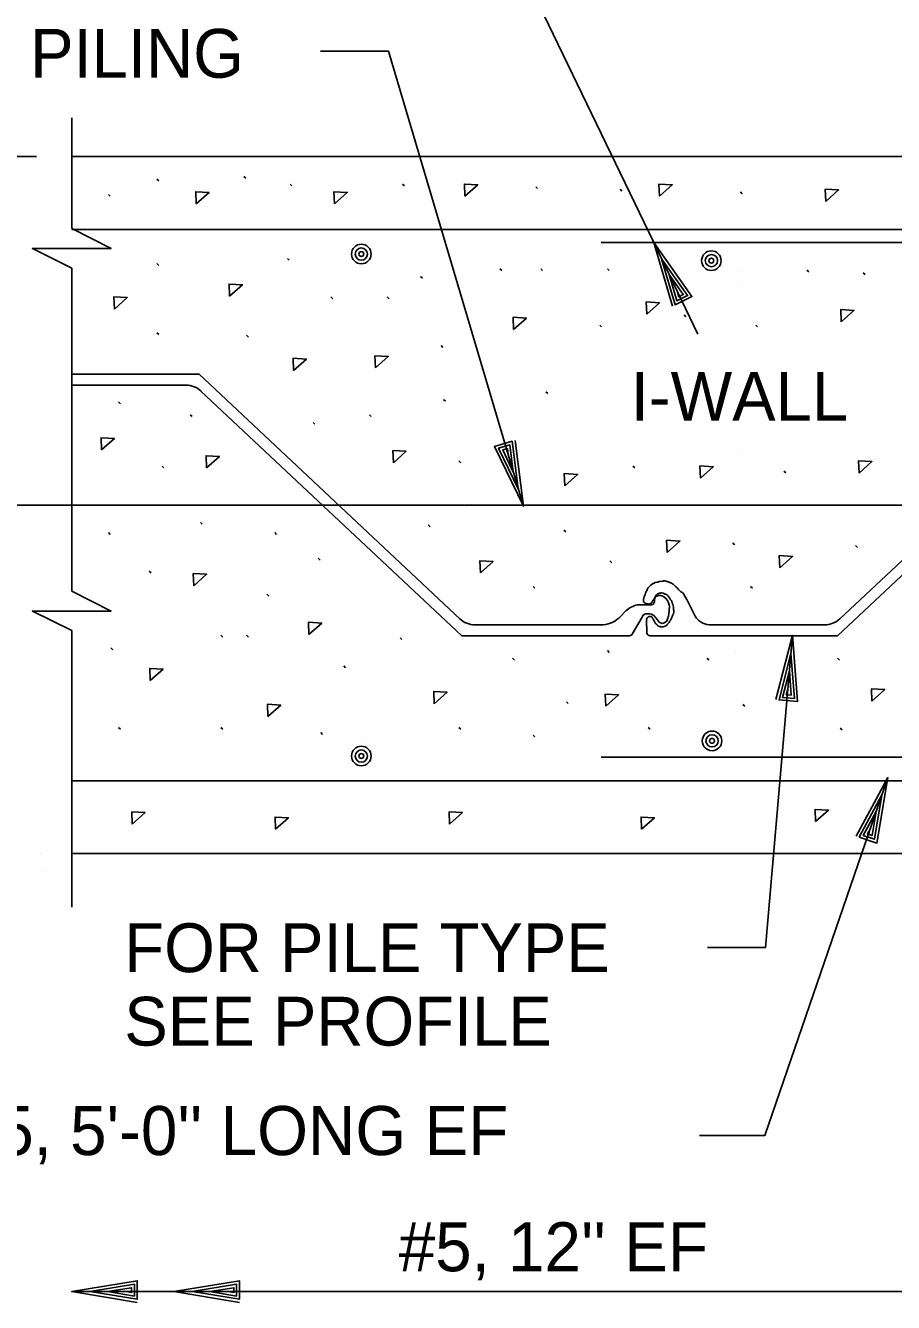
# Model space of a CAD drawing. Extents: x 22369.6 to 22428.3, y 22369.6 to 22415.
# Drawn here: x 22406.186 to 22409.492, y 22375.946 to 22380.805 of the extents above; entities that cross this region are included whole.
import ezdxf

# ---------------------------------------------------------------- set-up
doc = ezdxf.new("R2010")
doc.units = 0
for name, color, linetype in [('Level 1', 7, 'Continuous'), ('Level 10', 7, 'Continuous'), ('Level 2', 7, 'Continuous'), ('Level 4', 7, 'Continuous'), ('Level 8', 7, 'Continuous')]:
    doc.layers.add(name, color=color, linetype=linetype)

msp = doc.modelspace()

# ---------------------------------------------------------------- linework, layer by layer
at = {"layer": 'Level 1'}
for p, q in [((22406.3621, 22380.0321), (22406.3621, 22380.4539)), ((22406.2282, 22380.307), (22404.8457, 22380.307)), ((22408.5786, 22379.9799), (22408.5786, 22379.9799)), ((22408.6087, 22379.9175), (22408.6087, 22379.9175)), ((22406.3621, 22378.6522), (22406.3621, 22379.8821)), ((22408.9125, 22379.8706), (22408.9125, 22379.8706)), ((22408.9125, 22379.8267), (22408.9125, 22379.8267)), ((22408.9125, 22379.1883), (22408.9125, 22379.1883)), ((22408.9125, 22379.1193), (22408.9125, 22379.1193)), ((22407.9229, 22379.0406), (22407.9229, 22379.0406)), ((22408.0626, 22379.0419), (22408.0626, 22379.0419)), ((22405.5525, 22378.9803), (22411.9528, 22378.9803)), ((22407.8835, 22378.9836), (22407.8835, 22378.9836)), ((22408.0823, 22378.9754), (22408.0823, 22378.9754)), ((22406.3621, 22377.4502), (22406.3621, 22378.5022)), ((22408.9256, 22378.4828), (22408.9256, 22378.4828)), ((22409.1068, 22378.4847), (22409.1068, 22378.4847)), ((22408.8902, 22378.4236), (22408.8902, 22378.4236)), ((22409.1009, 22378.4156), (22409.1009, 22378.4156)), ((22408.8067, 22378.1314), (22408.8067, 22378.1314)), ((22407.4709, 22378.0812), (22407.4709, 22378.0812)), ((22408.7609, 22378.0873), (22408.7609, 22378.0873)), ((22407.4251, 22378.0296), (22407.4251, 22378.0296)), ((22409.4706, 22377.943), (22409.4706, 22377.943)), ((22409.448, 22377.8775), (22409.448, 22377.8775)), ((22406.2415, 22377.6528), (22406.2415, 22377.6528)), ((22406.2516, 22377.5845), (22406.2516, 22377.5845)), ((22406.9901, 22376.0149), (22406.9901, 22376.0149)), ((22407.0007, 22376.0283), (22407.0007, 22376.0283)), ((22406.3621, 22375.9869), (22410.1316, 22375.9869)), ((22406.3621, 22375.9869), (22406.3621, 22375.9869)), ((22406.4314, 22375.9869), (22406.4314, 22375.9869)), ((22406.9567, 22375.9869), (22406.9567, 22375.9869)), ((22406.9794, 22376.0016), (22406.9794, 22376.0016)), ((22406.9794, 22375.9829), (22406.9794, 22375.9829)), ((22406.9901, 22375.9696), (22406.9901, 22375.9696)), ((22407.0007, 22375.9576), (22407.0007, 22375.9576)), ((22407.0007, 22375.9456), (22407.0007, 22375.9456))]:
    msp.add_line(p, q, dxfattribs=at)
for points in [[(22407.6267, 22381.4145), (22407.8863, 22381.4145), (22408.5786, 22379.9799)], [(22407.3094, 22380.7069), (22407.5689, 22380.7069), (22408.0823, 22378.9754)], [(22408.5786, 22379.9799), (22408.7473, 22379.6304)], [(22408.6497, 22379.7374), (22408.5786, 22379.9799), (22408.7242, 22379.7734), (22408.6605, 22379.7426), (22408.6087, 22379.9175), (22408.7075, 22379.7772), (22408.6667, 22379.7575), (22408.6377, 22379.8575), (22408.6909, 22379.781), (22408.6741, 22379.7729), (22408.6678, 22379.795)], [(22408.0511, 22379.2262), (22408.0823, 22378.9754), (22407.9718, 22379.2027), (22408.0396, 22379.2228), (22408.0626, 22379.0419), (22407.9876, 22379.1963), (22408.0311, 22379.2091), (22408.0437, 22379.1058), (22408.0034, 22379.1898), (22408.0213, 22379.1951), (22408.024, 22379.1723)], [(22408.7831, 22377.2969), (22409.0046, 22377.2969), (22409.1068, 22378.4847)], [(22409.0443, 22378.2398), (22409.1068, 22378.4847), (22409.1266, 22378.2327), (22409.0562, 22378.2388), (22409.1009, 22378.4156), (22409.1143, 22378.2445), (22409.0691, 22378.2484), (22409.0952, 22378.3492), (22409.1019, 22378.2563), (22409.0833, 22378.2579), (22409.0892, 22378.2801)], [(22408.753, 22376.5806), (22409.0014, 22376.5806), (22409.4706, 22377.943)], [(22409.3503, 22377.7207), (22409.4706, 22377.943), (22409.4285, 22377.6938), (22409.3617, 22377.7168), (22409.448, 22377.8775), (22409.4194, 22377.7082), (22409.3765, 22377.723), (22409.4263, 22377.8144), (22409.4102, 22377.7227), (22409.3926, 22377.7287), (22409.4037, 22377.7489)], [(22406.6114, 22375.9456), (22406.3621, 22375.9869), (22406.6114, 22376.0283), (22406.6114, 22375.9576), (22406.4314, 22375.9869), (22406.6007, 22376.0149), (22406.6007, 22375.9696), (22406.4981, 22375.9869), (22406.5901, 22376.0016), (22406.5901, 22375.9829), (22406.5674, 22375.9869)], [(22407.0007, 22375.9456), (22406.7514, 22375.9869), (22407.0007, 22376.0283), (22407.0007, 22375.9576), (22406.8207, 22375.9869), (22406.9901, 22376.0149), (22406.9901, 22375.9696), (22406.8874, 22375.9869), (22406.9794, 22376.0016), (22406.9794, 22375.9829), (22406.9567, 22375.9869)]]:
    msp.add_lwpolyline(points, dxfattribs=at)
at = {"layer": 'Level 10'}
for p, q in [((22406.3621, 22380.307), (22410.3497, 22380.307)), ((22406.3621, 22380.0292), (22411.6716, 22380.0292)), ((22408.3785, 22379.9799), (22411.6681, 22379.9799)), ((22408.3785, 22378.0214), (22411.15, 22378.0214)), ((22406.3621, 22377.9313), (22411.1526, 22377.9313)), ((22406.3621, 22377.6536), (22411.3171, 22377.6536))]:
    msp.add_line(p, q, dxfattribs=at)
at = {"layer": 'Level 2'}
for p, q in [((22406.3621, 22379.4778), (22406.8468, 22379.4778)), ((22406.8468, 22379.4778), (22407.8413, 22378.5463)), ((22409.2862, 22378.5463), (22410.2807, 22379.4778)), ((22406.7977, 22379.4363), (22406.3621, 22379.4363)), ((22406.854, 22379.4142), (22407.8484, 22378.4828)), ((22409.279, 22378.4828), (22410.2735, 22379.4142)), ((22408.5164, 22378.6009), (22408.563, 22378.6007)), ((22408.7046, 22378.6214), (22408.7359, 22378.5577)), ((22408.452, 22378.5564), (22408.4721, 22378.578)), ((22408.4969, 22378.4887), (22408.5351, 22378.5534)), ((22408.5519, 22378.4964), (22408.5517, 22378.541)), ((22407.8976, 22378.5242), (22408.3876, 22378.5242)), ((22409.2299, 22378.5242), (22408.7896, 22378.5242)), ((22407.8484, 22378.4828), (22408.4867, 22378.4828)), ((22408.5639, 22378.4828), (22409.279, 22378.4828))]:
    msp.add_line(p, q, dxfattribs=at)
for points in [[(22408.5719, 22378.6096), (22408.5708, 22378.6085), (22408.5681, 22378.6068), (22408.5675, 22378.6068), (22408.5653, 22378.6047), (22408.5635, 22378.6042), (22408.563, 22378.6037), (22408.5598, 22378.6035), (22408.5587, 22378.6035), (22408.5572, 22378.6038), (22408.5562, 22378.6038), (22408.5547, 22378.6042), (22408.5537, 22378.604), (22408.5529, 22378.6043), (22408.552, 22378.6045), (22408.5502, 22378.6053), (22408.548, 22378.6058), (22408.5469, 22378.6063), (22408.5462, 22378.6068), (22408.5454, 22378.6076), (22408.5422, 22378.6095), (22408.5411, 22378.61), (22408.5407, 22378.6108), (22408.5397, 22378.6116), (22408.5392, 22378.6129), (22408.5391, 22378.6158), (22408.5394, 22378.6191), (22408.5396, 22378.6222), (22408.5401, 22378.6236), (22408.5404, 22378.6251), (22408.5409, 22378.6265), (22408.5409, 22378.6284), (22408.5437, 22378.6337), (22408.5449, 22378.6367), (22408.5449, 22378.6377), (22408.5454, 22378.6393), (22408.5456, 22378.6403), (22408.5472, 22378.6443), (22408.5482, 22378.6473), (22408.5497, 22378.6512), (22408.5504, 22378.6521), (22408.5519, 22378.6536), (22408.5537, 22378.6572), (22408.5543, 22378.6592), (22408.5555, 22378.6619), (22408.5567, 22378.6639), (22408.557, 22378.6645), (22408.5575, 22378.6657), (22408.5582, 22378.6667), (22408.5597, 22378.668), (22408.5618, 22378.6695), (22408.5625, 22378.6702), (22408.5636, 22378.671), (22408.5643, 22378.672), (22408.5648, 22378.6723), (22408.5661, 22378.6745), (22408.5681, 22378.676), (22408.5704, 22378.677), (22408.5708, 22378.6776), (22408.5767, 22378.6819), (22408.5804, 22378.6834), (22408.582, 22378.6844), (22408.5839, 22378.6849), (22408.5854, 22378.6854), (22408.59, 22378.6862), (22408.592, 22378.6866), (22408.5941, 22378.6872), (22408.5968, 22378.6886), (22408.5991, 22378.6889), (22408.6019, 22378.6899), (22408.6043, 22378.6899), (22408.6134, 22378.6906), (22408.6157, 22378.6912), (22408.619, 22378.6914), (22408.621, 22378.6912), (22408.6238, 22378.6906), (22408.6276, 22378.6904), (22408.6296, 22378.6899), (22408.6323, 22378.6884), (22408.6341, 22378.6877), (22408.6363, 22378.6872), (22408.6371, 22378.6866), (22408.6429, 22378.6847), (22408.6442, 22378.6844), (22408.6467, 22378.6833), (22408.6502, 22378.6804)], [(22408.5351, 22378.5534), (22408.5369, 22378.5584), (22408.5364, 22378.5584), (22408.5434, 22378.5652), (22408.5469, 22378.5662), (22408.5623, 22378.5667), (22408.5699, 22378.5654), (22408.5792, 22378.5594), (22408.5885, 22378.5498), (22408.5915, 22378.5443), (22408.5928, 22378.5431), (22408.5937, 22378.5403), (22408.5998, 22378.5345), (22408.6043, 22378.5317), (22408.6114, 22378.5292), (22408.6185, 22378.5314), (22408.6285, 22378.5388), (22408.6315, 22378.5476), (22408.6348, 22378.5572), (22408.6368, 22378.5649), (22408.6391, 22378.5947), (22408.6386, 22378.5944), (22408.6378, 22378.6002), (22408.6361, 22378.6043), (22408.6338, 22378.6123), (22408.631, 22378.6169), (22408.6253, 22378.6247), (22408.6177, 22378.6306), (22408.6135, 22378.633), (22408.6043, 22378.6362), (22408.6031, 22378.6358), (22408.6026, 22378.6365), (22408.5988, 22378.6358), (22408.5965, 22378.636), (22408.59, 22378.6335), (22408.5878, 22378.633), (22408.5878, 22378.6322), (22408.5845, 22378.6289), (22408.582, 22378.6226), (22408.5814, 22378.6135), (22408.5812, 22378.6113), (22408.5781, 22378.6042), (22408.5709, 22378.6005), (22408.5706, 22378.6014), (22408.5706, 22378.6009), (22408.563, 22378.6007)], [(22408.653, 22378.565), (22408.6535, 22378.5662), (22408.6548, 22378.5722), (22408.6548, 22378.5733), (22408.6548, 22378.5745), (22408.655, 22378.5761), (22408.655, 22378.5785), (22408.654, 22378.5826), (22408.6538, 22378.5841), (22408.6537, 22378.5846), (22408.654, 22378.5854), (22408.6537, 22378.5859), (22408.654, 22378.5872), (22408.6538, 22378.5884), (22408.6542, 22378.5897), (22408.6538, 22378.5914), (22408.6524, 22378.5962), (22408.651, 22378.602), (22408.6507, 22378.6035), (22408.65, 22378.6047), (22408.6497, 22378.6058), (22408.6497, 22378.6066), (22408.6492, 22378.6076), (22408.6489, 22378.609), (22408.6487, 22378.61), (22408.6482, 22378.611), (22408.648, 22378.612), (22408.6472, 22378.6139), (22408.6469, 22378.6153), (22408.6462, 22378.6169), (22408.6442, 22378.6189), (22408.6429, 22378.6201), (22408.6417, 22378.6226), (22408.6392, 22378.6269), (22408.6387, 22378.628), (22408.6381, 22378.6287), (22408.6364, 22378.6312), (22408.6349, 22378.6325), (22408.6341, 22378.6328), (22408.6336, 22378.6337), (22408.6323, 22378.6348), (22408.6306, 22378.637), (22408.6293, 22378.6382), (22408.6286, 22378.6387), (22408.628, 22378.6391), (22408.6273, 22378.6395), (22408.6267, 22378.6398), (22408.6257, 22378.6401), (22408.6232, 22378.641), (22408.6217, 22378.6413), (22408.6192, 22378.6428), (22408.6152, 22378.6446), (22408.6142, 22378.6451), (22408.6097, 22378.6461), (22408.6079, 22378.6458), (22408.6067, 22378.6458), (22408.6051, 22378.6453), (22408.6039, 22378.6451), (22408.6029, 22378.645), (22408.6006, 22378.6446), (22408.6, 22378.6446), (22408.5976, 22378.6436), (22408.5963, 22378.6435), (22408.5946, 22378.6428), (22408.5935, 22378.6418), (22408.5927, 22378.6413), (22408.5915, 22378.6406), (22408.5907, 22378.64), (22408.59, 22378.639), (22408.5893, 22378.6387), (22408.589, 22378.638), (22408.588, 22378.6373), (22408.5873, 22378.6367), (22408.5865, 22378.6357), (22408.5849, 22378.6322), (22408.5832, 22378.6284), (22408.5824, 22378.627), (22408.5809, 22378.6247), (22408.5802, 22378.6232), (22408.5774, 22378.6189), (22408.5756, 22378.6169), (22408.5746, 22378.6144), (22408.5742, 22378.6138), (22408.5734, 22378.6128), (22408.5729, 22378.6113), (22408.5719, 22378.6096)], [(22408.6502, 22378.6804), (22408.653, 22378.6785), (22408.655, 22378.677), (22408.6562, 22378.6753), (22408.6588, 22378.6733), (22408.6605, 22378.6713), (22408.6616, 22378.6707), (22408.6621, 22378.6702), (22408.6643, 22378.669), (22408.6655, 22378.6677), (22408.6658, 22378.6668), (22408.6676, 22378.6649), (22408.6686, 22378.6634), (22408.6734, 22378.6589), (22408.6737, 22378.6574), (22408.6761, 22378.6559), (22408.6769, 22378.6549), (22408.681, 22378.6511), (22408.6844, 22378.6493), (22408.6878, 22378.6474), (22408.6885, 22378.6468), (22408.6897, 22378.6455), (22408.6908, 22378.6448), (22408.6925, 22378.6425), (22408.6928, 22378.6416), (22408.6932, 22378.641), (22408.6936, 22378.64), (22408.6936, 22378.6401), (22408.6938, 22378.6403), (22408.7046, 22378.6214)], [(22408.5517, 22378.541), (22408.5522, 22378.5418), (22408.552, 22378.5433), (22408.5517, 22378.5433), (22408.5517, 22378.5445), (22408.5514, 22378.5463), (22408.5515, 22378.5468), (22408.5515, 22378.5466), (22408.5515, 22378.5473), (22408.5522, 22378.5479), (22408.5525, 22378.5488), (22408.5535, 22378.5508), (22408.5535, 22378.5508), (22408.5553, 22378.5529), (22408.5557, 22378.5531), (22408.5565, 22378.5541), (22408.5578, 22378.5549), (22408.559, 22378.5554), (22408.5618, 22378.5559), (22408.5648, 22378.5562), (22408.5665, 22378.5562), (22408.5679, 22378.5559), (22408.5713, 22378.5547), (22408.5721, 22378.5534), (22408.5722, 22378.5519), (22408.5734, 22378.5506), (22408.5737, 22378.5493), (22408.5761, 22378.5473), (22408.5762, 22378.5468), (22408.5777, 22378.5435), (22408.5794, 22378.5411), (22408.5812, 22378.5392), (22408.5822, 22378.536), (22408.5829, 22378.535), (22408.584, 22378.533), (22408.5845, 22378.5324), (22408.5859, 22378.5295), (22408.5862, 22378.529), (22408.587, 22378.5285), (22408.5878, 22378.5275), (22408.5907, 22378.5251), (22408.5908, 22378.5246), (22408.5915, 22378.5239), (22408.5922, 22378.5227), (22408.5928, 22378.5219), (22408.5946, 22378.5206), (22408.5961, 22378.5199), (22408.5976, 22378.5189), (22408.5998, 22378.5183), (22408.6008, 22378.5178), (22408.6019, 22378.5178), (22408.6026, 22378.5174), (22408.6062, 22378.5171), (22408.6081, 22378.5169), (22408.6124, 22378.5173), (22408.6134, 22378.5171), (22408.615, 22378.5171), (22408.6187, 22378.5179), (22408.6228, 22378.5196), (22408.6237, 22378.5201), (22408.6247, 22378.5206), (22408.6257, 22378.5212), (22408.627, 22378.5222), (22408.6281, 22378.5229), (22408.6285, 22378.5236), (22408.6303, 22378.5252), (22408.6313, 22378.5266), (22408.6359, 22378.5317), (22408.6369, 22378.5332), (22408.6387, 22378.5365), (22408.6407, 22378.5396), (22408.6414, 22378.5405), (22408.6417, 22378.5415), (22408.6426, 22378.5421), (22408.6439, 22378.5446), (22408.6456, 22378.5478), (22408.6465, 22378.5499), (22408.6484, 22378.5552), (22408.6484, 22378.5559), (22408.6489, 22378.5567), (22408.6492, 22378.5577), (22408.6497, 22378.5586), (22408.6509, 22378.562), (22408.6515, 22378.5634), (22408.653, 22378.565)]]:
    msp.add_lwpolyline(points, dxfattribs=at)
for centre, radius in [((22407.465, 22379.9355), 0.0373), ((22407.465, 22379.9355), 0.0233), ((22408.7983, 22379.9103), 0.0373), ((22407.465, 22379.9355), 0.00933), ((22408.7983, 22379.9103), 0.0233), ((22408.7983, 22379.9103), 0.00933), ((22408.8008, 22378.0828), 0.0373), ((22408.8008, 22378.0828), 0.0233), ((22407.465, 22378.0251), 0.0373), ((22408.8008, 22378.0828), 0.00933), ((22407.465, 22378.0251), 0.0233), ((22407.465, 22378.0251), 0.00933)]:
    msp.add_circle(centre, radius, dxfattribs=at)
for centre, radius, start, end in [((22406.7976, 22379.3534), 0.0829, 46.5301, 90), ((22408.5464, 22378.4888), 0.116, 104.9327, 129.732), ((22407.8976, 22378.6072), 0.0829, 225.9589, 270), ((22407.8976, 22378.6072), 0.0829, 226.5263, 227.2156), ((22408.3773, 22378.6257), 0.1019, 275.7693, 317.1676), ((22408.7969, 22378.5956), 0.0717, 211.905, 264.1589), ((22409.2299, 22378.6072), 0.0829, 270, 313.4699), ((22408.4855, 22378.4966), 0.0139, 275.0736, 325.5224), ((22408.5657, 22378.4965), 0.0138, 180.2909, 270.0528)]:
    msp.add_arc(centre, radius, start, end, dxfattribs=at)
at = {"layer": 'Level 8'}
for p, q in [((22406.6936, 22380.214), (22406.6866, 22380.221)), ((22407.025, 22380.2237), (22407.018, 22380.2308)), ((22407.2005, 22380.1945), (22407.1934, 22380.2015)), ((22407.6293, 22380.1945), (22407.6223, 22380.2015)), ((22408.1361, 22380.1847), (22408.1291, 22380.1917)), ((22406.5084, 22380.1555), (22406.5014, 22380.1625)), ((22408.4578, 22380.175), (22408.4507, 22380.182)), ((22408.9159, 22380.1652), (22408.9088, 22380.1722)), ((22406.6936, 22379.8921), (22406.6866, 22379.8992)), ((22407.1907, 22379.9116), (22407.1837, 22379.9187)), ((22407.6976, 22379.8434), (22407.6905, 22379.8504)), ((22407.9997, 22379.8726), (22407.9927, 22379.8797)), ((22408.1556, 22379.8726), (22408.1486, 22379.8797)), ((22408.4091, 22379.8726), (22408.402, 22379.8797)), ((22409.1693, 22379.8674), (22409.1623, 22379.8744)), ((22409.3837, 22379.857), (22409.3767, 22379.864)), ((22407.3564, 22379.7653), (22407.3494, 22379.7724)), ((22407.5708, 22379.7653), (22407.5638, 22379.7724)), ((22408.7015, 22379.6971), (22408.6944, 22379.7041)), ((22408.3798, 22379.6581), (22408.3728, 22379.6651)), ((22408.9744, 22379.6581), (22408.9673, 22379.6651)), ((22406.6936, 22379.6288), (22406.6866, 22379.6359)), ((22407.0348, 22379.6191), (22407.0277, 22379.6261)), ((22407.7755, 22379.58), (22407.7685, 22379.5871)), ((22406.5474, 22379.3655), (22406.5404, 22379.3725)), ((22407.7853, 22379.3752), (22407.7782, 22379.3823)), ((22408.1751, 22379.4045), (22408.1681, 22379.4115)), ((22406.8203, 22379.3167), (22406.8133, 22379.3238)), ((22407.5026, 22379.3167), (22407.4956, 22379.3238)), ((22407.2882, 22379.2875), (22407.2811, 22379.2945)), ((22406.7131, 22379.1217), (22406.7061, 22379.1287)), ((22407.8437, 22379.1412), (22407.8367, 22379.1482)), ((22408.5065, 22379.1217), (22408.4995, 22379.1287)), ((22409.0816, 22379.1022), (22409.0745, 22379.1092)), ((22406.8593, 22378.9071), (22406.8523, 22378.9142)), ((22407.7268, 22378.8974), (22407.7197, 22378.9044)), ((22408.2434, 22378.8779), (22408.2363, 22378.8849)), ((22406.5085, 22378.8681), (22406.5014, 22378.8752)), ((22407.142, 22378.8681), (22407.135, 22378.8752)), ((22408.8866, 22378.8291), (22408.8796, 22378.8361)), ((22409.3545, 22378.8193), (22409.3474, 22378.8264)), ((22407.3077, 22378.7706), (22407.3006, 22378.7776)), ((22408.4188, 22378.7608), (22408.4118, 22378.7679)), ((22406.6644, 22378.7218), (22406.6574, 22378.7289)), ((22407.1127, 22378.6341), (22407.1057, 22378.6411)), ((22408.1264, 22378.6633), (22408.1194, 22378.6703)), ((22408.9549, 22378.6633), (22408.9478, 22378.6703)), ((22406.9373, 22378.478), (22406.9303, 22378.4851)), ((22407.0348, 22378.478), (22407.0277, 22378.4851)), ((22407.6196, 22378.4683), (22407.6125, 22378.4753)), ((22406.5182, 22378.4292), (22406.5112, 22378.4363)), ((22408.0484, 22378.3902), (22408.0414, 22378.3973)), ((22408.4091, 22378.4195), (22408.402, 22378.4265)), ((22408.7892, 22378.3902), (22408.7821, 22378.3973)), ((22409.2862, 22378.3902), (22409.2792, 22378.3973)), ((22407.4052, 22378.361), (22407.3981, 22378.368)), ((22408.2531, 22378.2244), (22408.2461, 22378.2315)), ((22408.9256, 22378.2147), (22408.9186, 22378.2217)), ((22406.5474, 22378.1269), (22406.5404, 22378.134)), ((22406.9373, 22378.1269), (22406.9303, 22378.134)), ((22407.3174, 22378.1074), (22407.3104, 22378.1145)), ((22407.8437, 22378.1269), (22407.8367, 22378.134)), ((22408.1264, 22378.0977), (22408.1194, 22378.1047)), ((22408.565, 22378.1269), (22408.558, 22378.134)), ((22409.296, 22378.1247), (22409.289, 22378.1317))]:
    msp.add_line(p, q, dxfattribs=at)
for points in [[(22407.8598, 22380.1554), (22407.8579, 22380.2018), (22407.9086, 22380.199)], [(22408.6005, 22380.1554), (22408.5987, 22380.2018), (22408.6493, 22380.199)], [(22406.8364, 22380.1261), (22406.8346, 22380.1725), (22406.8852, 22380.1697)], [(22407.3627, 22380.1261), (22407.3609, 22380.1725), (22407.4115, 22380.1697)], [(22409.2341, 22380.1359), (22409.2322, 22380.1823), (22409.2829, 22380.1795)], [(22406.9631, 22379.775), (22406.9612, 22379.8214), (22407.0119, 22379.8186)], [(22406.5245, 22379.7262), (22406.5226, 22379.7727), (22406.5733, 22379.7699)], [(22408.5518, 22379.7067), (22408.5499, 22379.7532), (22408.6006, 22379.7504)], [(22409.2926, 22379.6775), (22409.2907, 22379.7239), (22409.3413, 22379.7211)], [(22408.045, 22379.6482), (22408.0431, 22379.6947), (22408.0938, 22379.6918)], [(22407.2068, 22379.4922), (22407.2049, 22379.5386), (22407.2556, 22379.5358)], [(22407.5187, 22379.5019), (22407.5168, 22379.5484), (22407.5674, 22379.5456)], [(22406.4758, 22379.1899), (22406.4739, 22379.2363), (22406.5246, 22379.2335)], [(22407.5869, 22379.1411), (22407.585, 22379.1875), (22407.6357, 22379.1847)], [(22406.8754, 22379.1216), (22406.8735, 22379.168), (22406.9242, 22379.1652)], [(22408.7565, 22379.0826), (22408.7546, 22379.129), (22408.8053, 22379.1262)], [(22409.3608, 22379.1021), (22409.3589, 22379.1485), (22409.4096, 22379.1457)], [(22408.2399, 22379.0533), (22408.2381, 22379.0997), (22408.2887, 22379.0969)], [(22408.6298, 22378.7997), (22408.6279, 22378.8462), (22408.6786, 22378.8434)], [(22409.0586, 22378.7412), (22409.0568, 22378.7877), (22409.1074, 22378.7848)], [(22407.9183, 22378.7217), (22407.9164, 22378.7682), (22407.9671, 22378.7653)], [(22406.8267, 22378.673), (22406.8248, 22378.7194), (22406.8754, 22378.7166)], [(22407.2653, 22378.4877), (22407.2634, 22378.5341), (22407.314, 22378.5313)], [(22406.661, 22378.3121), (22406.6591, 22378.3586), (22406.7098, 22378.3557)], [(22407.7428, 22378.2243), (22407.741, 22378.2708), (22407.7916, 22378.268)], [(22408.3959, 22378.2146), (22408.394, 22378.261), (22408.4446, 22378.2582)], [(22409.4095, 22378.2341), (22409.4076, 22378.2805), (22409.4583, 22378.2777)], [(22407.1093, 22378.1756), (22407.1074, 22378.222), (22407.1581, 22378.2192)], [(22406.5927, 22377.766), (22406.5909, 22377.8124), (22406.6415, 22377.8096)], [(22407.8013, 22377.766), (22407.7995, 22377.8124), (22407.8501, 22377.8096)], [(22409.1951, 22377.7757), (22409.1932, 22377.8222), (22409.2439, 22377.8193)], [(22407.1386, 22377.7465), (22407.1367, 22377.7929), (22407.1873, 22377.7901)], [(22408.5323, 22377.7465), (22408.5305, 22377.7929), (22408.5811, 22377.7901)]]:
    msp.add_lwpolyline(points, close=True, dxfattribs=at)
for points in [[(22406.3621, 22379.8821), (22406.2121, 22379.9566), (22406.5117, 22379.9566), (22406.3621, 22380.0321)], [(22406.3621, 22378.5022), (22406.2121, 22378.5767), (22406.5117, 22378.5767), (22406.3621, 22378.6522)]]:
    msp.add_lwpolyline(points, dxfattribs=at)

# ---------------------------------------------------------------- texts
at = {"layer": 'Level 4'}
for s, height, p in [('SHEET PILING', 0.185729, (22405.3064, 22380.6064)), ('I-WALL', 0.18573, (22408.4913, 22379.3008)), ('FOR PILE TYPE', 0.185729, (22406.5621, 22377.2026)), ('SEE PROFILE', 0.185729, (22406.5621, 22376.9231)), ("#5, 5'-0'' LONG EF", 0.186667, (22405.9395, 22376.5064)), ("#5, 12'' EF", 0.186667, (22407.6074, 22376.0643))]:
    msp.add_text(s, height=height, dxfattribs=at).set_placement(p)

doc.saveas('drawing.dxf')
